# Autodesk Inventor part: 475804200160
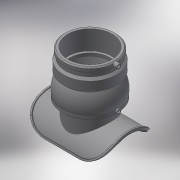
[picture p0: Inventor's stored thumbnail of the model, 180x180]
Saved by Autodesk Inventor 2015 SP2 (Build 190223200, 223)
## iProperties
Created: 2017-08
Part Number: 475804200160
Material: Generic
Description: PLASSON WASTEWATER SADDLE 200X160 EF ADJUSTABLE INLET
Document SubType Name: Modeling
Designer: Кирилл
Density: 1 g/cm^3
Appearance: Default
Author: Кирилл
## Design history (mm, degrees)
derived "475804.ipt"
feature "Solid1::475804.ipt"
feature "Solid2::475804.ipt"
tag "TaggingFeature1"
body "Solid1"
body "Solid2"
other parameters: "d0" = 161.6, "d3" = 45 deg, "d4" = 184, "d5" = 176, "d6" = 142.208, "d7" = 129.28, "d8" = 144, "d13" = 45 deg, "d15" = 135 deg, "d17" = 192, "d18" = 45 deg, "d19" = 80.8, "d22" = 4, "d23" = 16.16, "d25" = 45 deg, "d26" = 15 deg, "d27" = 262.6, "d28" = 136, "d29" = 156.8, "d32" = 202, "d37" = 0, "d38" = 208, "d39" = 104, "d40" = 218, "d42" = 0, "d52" = 83.2, "d53" = 6.24, "d55" = 0.832, "d56" = 224, "d57" = 0, "d58" = 105, "d59" = 15, "d61" = 5 deg, "d62" = 15, "d65" = 4, "d66" = 4, "d67" = 14, "d68" = 0, "d69" = 3, "d70" = 0, "B_" = 208, "H_" = 202, "A_" = 105, "d21" = 4
